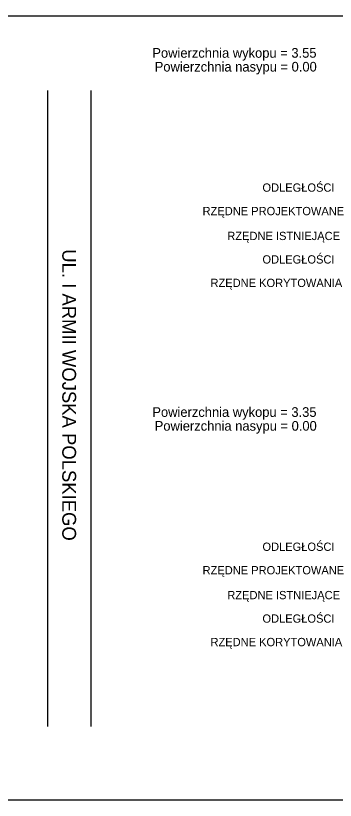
# Model space of a CAD drawing. Extents: x 7492871 to 7493499, y 5802964 to 5802992.
# Drawn here: x 7493040.9 to 7493052.48, y 5802963.88 to 5802992.28 of the extents above; entities that cross this region are included whole.
import ezdxf

# ---------------------------------------------------------------- set-up
doc = ezdxf.new("R2010")
doc.units = 0
for name, color, linetype in [('_wydruk', 7, 'Continuous'), ('d_pop_nasyp_opis', 7, 'Continuous'), ('d_pop_wykop_opis', 7, 'Continuous'), ('opisy_ramki_pop', 7, 'Continuous'), ('pop_opis', 7, 'Continuous'), ('pop_pikietaz', 7, 'Continuous')]:
    doc.layers.add(name, color=color, linetype=linetype)

msp = doc.modelspace()

# ---------------------------------------------------------------- linework, layer by layer
at = {"layer": '_wydruk'}
msp.add_lwpolyline([(7492871.369, 5802992.281), (7493499.283, 5802992.281), (7493499.283, 5802963.881), (7492871.369, 5802963.881)], close=True, dxfattribs=at)
at = {"layer": 'opisy_ramki_pop'}
for p, q in [((7493042.058, 5802989.573), (7493042.058, 5802966.547)), ((7493043.624, 5802989.573), (7493043.624, 5802966.547))]:
    msp.add_line(p, q, dxfattribs=at)

# ---------------------------------------------------------------- texts
at = {"layer": 'd_pop_nasyp_opis'}
for p in [(7493045.938, 5802990.259), (7493045.938, 5802977.259)]:
    msp.add_text('Powierzchnia nasypu = 0.00', height=0.35, dxfattribs=at).set_placement(p)
at = {"layer": 'd_pop_wykop_opis'}
for s, p in [('Powierzchnia wykopu = 3.55', (7493045.852, 5802990.759)), ('Powierzchnia wykopu = 3.35', (7493045.852, 5802977.759))]:
    msp.add_text(s, height=0.35, dxfattribs=at).set_placement(p)
at = {"layer": 'pop_opis'}
for s, p in [('ODLEGŁOŚCI', (7493049.839, 5802985.909)), ('ODLEGŁOŚCI', (7493049.839, 5802985.909)), ('ODLEGŁOŚCI', (7493049.839, 5802985.909)), ('ODLEGŁOŚCI', (7493049.839, 5802985.909)), ('RZĘDNE PROJEKTOWANE', (7493047.671, 5802985.059)), ('RZĘDNE PROJEKTOWANE', (7493047.671, 5802985.059)), ('RZĘDNE PROJEKTOWANE', (7493047.671, 5802985.059)), ('RZĘDNE PROJEKTOWANE', (7493047.671, 5802985.059)), ('RZĘDNE ISTNIEJĄCE', (7493048.567, 5802984.159)), ('ODLEGŁOŚCI', (7493049.839, 5802983.309)), ('RZĘDNE KORYTOWANIA', (7493047.957, 5802982.459)), ('ODLEGŁOŚCI', (7493049.839, 5802972.909)), ('ODLEGŁOŚCI', (7493049.839, 5802972.909)), ('ODLEGŁOŚCI', (7493049.839, 5802972.909)), ('ODLEGŁOŚCI', (7493049.839, 5802972.909)), ('RZĘDNE PROJEKTOWANE', (7493047.671, 5802972.059)), ('RZĘDNE PROJEKTOWANE', (7493047.671, 5802972.059)), ('RZĘDNE PROJEKTOWANE', (7493047.671, 5802972.059)), ('RZĘDNE PROJEKTOWANE', (7493047.671, 5802972.059)), ('RZĘDNE ISTNIEJĄCE', (7493048.567, 5802971.159)), ('ODLEGŁOŚCI', (7493049.839, 5802970.309)), ('RZĘDNE KORYTOWANIA', (7493047.957, 5802969.459))]:
    msp.add_text(s, height=0.3, dxfattribs=at).set_placement(p)
at = {"layer": 'pop_pikietaz'}
msp.add_text('UL. I ARMII WOJSKA POLSKIEGO', height=0.5, rotation=270, dxfattribs=at).set_placement((7493042.591, 5802983.826))

doc.saveas('drawing.dxf')
